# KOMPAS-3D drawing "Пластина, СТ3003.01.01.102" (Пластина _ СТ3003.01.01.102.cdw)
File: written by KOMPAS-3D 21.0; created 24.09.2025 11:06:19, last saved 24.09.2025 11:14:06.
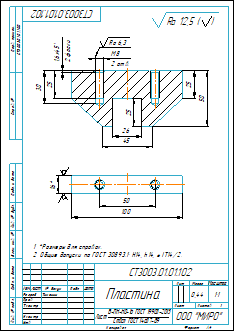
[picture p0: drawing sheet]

Sheet 1: A4, portrait

Document properties: Знак неуказанной шероховатости: 4; Параметр неуказанной шероховатости: Ra 12,5; Масса: 0.442831; Полное имя файла: ..\..\..\3D\Кронштейн _ СТ3003.01.01.000\Основание _ СТ3003.01.01.100\Пластина _ СТ3003.01.01.102.m3d

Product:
- Part/product: Пластина  | designation СТ3003.01.01.102
    Материал: Лист$dБ-ПН-НО-16 ГОСТ 19903-2015;Ст3сп ГОСТ 14637-89$ (density 7850 kg/m3)
    Масса: 0.442831

Title block, sheet 1: Наименование: Пластина; designation: СТ3003.01.01.102; Материал: Лист Б-ПН-НО-16 ГОСТ 19903-2015 Ст3сп ГОСТ 14637-89; Масса: 0,44; Количество листов документа: 1; organisation: ООО "МИРО"; Форматы листов документа: A4; stored path: C:\Users\1\Yandex.Disk\Документы\Новая папка\Стапель №2\Стапель _ СТ3003.00.00.000\Опора _ СТ3003.01.00.000\2D\Кронштейн _ СТ3003.01.01.000\Основание _ СТ3003.01.01.100\Пластина _ СТ3003.01.01.102.cdw; Разработал: Тимонин

Views: Вид 1, Местный разрез 1, Слева, Проекционный вид 2
Referenced files in C:\Users\1\Yandex.Disk\Документы\Новая папка\Стапель №2\Стапель _ СТ3003.00.00.000\Опора _ СТ3003.01.00.000\3D\Кронштейн _ СТ3003.01.01.000\Основание _ СТ3003.01.01.100\: Пластина _ СТ3003.01.01.102.m3d
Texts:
  Ra 6,3
  Ra 12,5
  Ra 12,5 ( )
  СТ3003.01.01.100
  СТ3003.01.01.102 Пластина
Dimensions and other numbers on the sheet: 1,6; 2 фаски; 8; 2 отв.; 26; 25; 50; 45; 30; 16; 100; 1:1; 1; 0,44

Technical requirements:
  *Размеры для справок.
  Общие допуски по ГОСТ 30893.1: Н14, h14, ± IT14/2.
